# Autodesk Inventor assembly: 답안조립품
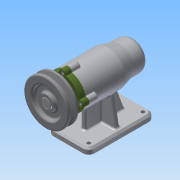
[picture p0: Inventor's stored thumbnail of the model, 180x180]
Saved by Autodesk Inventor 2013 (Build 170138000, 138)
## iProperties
Created: 2019-07
Part Number: 답안조립품
Document SubType Name: Assembly
Designer: Administrator
Author: Administrator
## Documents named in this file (12)
- C:\Users\Administrator\Desktop\490704V1050\답안조립품.iam
- C:\Users\Administrator\Desktop\490704V1050\본체.ipt
- C:\Users\Administrator\Desktop\490704V1050\V벨트풀리.ipt
- C:\Users\Administrator\Desktop\490704V1050\멈춤나사 M3.ipt
- C:\Users\Administrator\Desktop\490704V1050\베어링 6004.ipt
- C:\Users\Administrator\Desktop\490704V1050\베어링 51202.ipt
- C:\Users\Administrator\Desktop\490704V1050\볼트 M4.ipt
- C:\Users\Administrator\Desktop\490704V1050\어댑터슬리브.ipt
- C:\Users\Administrator\Desktop\490704V1050\오일 실.ipt
- C:\Users\Administrator\Desktop\490704V1050\축.ipt
- C:\Users\Administrator\Desktop\490704V1050\커버.ipt
- C:\Users\Administrator\Desktop\490704V1050\키 5 x 5 x 16.ipt
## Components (1 placed, 1 different names)
1. V벨트풀리:1 — 각도:2
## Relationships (1: Angle 1)
- 각도:2 [Angle]: V벨트풀리:1
